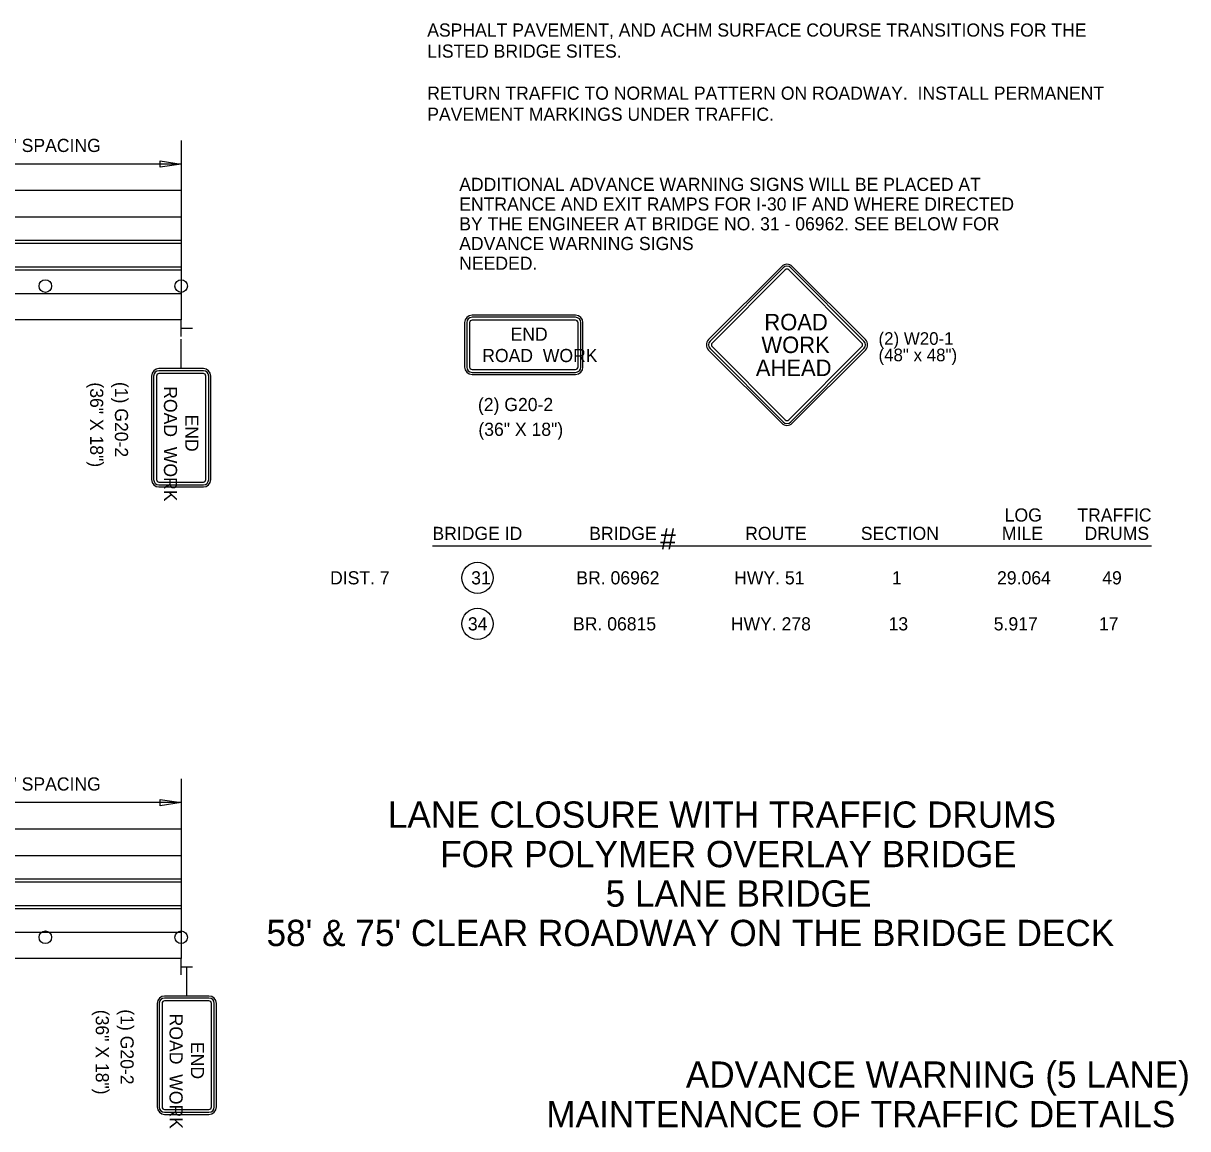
# Model space of a CAD drawing. Extents: x 1930579 to 1937984, y 596452 to 597630.
# Drawn here: x 1937427 to 1937958, y 596606 to 597111 of the extents above; entities that cross this region are included whole.
import ezdxf

# ---------------------------------------------------------------- set-up
doc = ezdxf.new("R2010")
doc.units = 0
for name, color, linetype in [('Default', 7, 'Continuous'), ('P_TC_Signs_Temporary', 7, 'Continuous'), ('R_Annotation', 7, 'Continuous')]:
    doc.layers.add(name, color=color, linetype=linetype)

msp = doc.modelspace()

# ---------------------------------------------------------------- linework, layer by layer
at = {"layer": 'Default'}
for p, q in [((1937498.74, 597057.24), (1937498.74, 596975.31)), ((1937489.08, 597045), (1937489.08, 597047.9)), ((1937489.08, 597047.9), (1937498.74, 597046.45)), ((1937498.74, 597046.45), (1937332.4, 597046.45)), ((1937498.74, 597046.45), (1937489.08, 597045)), ((1937498.74, 597034.31), (1936493.11, 597034.31)), ((1936493.11, 597022.31), (1937498.74, 597022.31)), ((1937498.74, 597011.52), (1936493.11, 597011.52)), ((1937498.74, 597010.14), (1936493.11, 597010.14)), ((1937498.74, 596999.41), (1936493.11, 596999.41)), ((1937498.74, 596998.03), (1936493.11, 596998.03)), ((1936493.11, 596987.31), (1937498.74, 596987.31)), ((1937498.74, 596975.31), (1936493.11, 596975.31)), ((1937498.63, 596975.29), (1937498.63, 596967.81)), ((1937498.74, 596971.57), (1937503.84, 596971.57)), ((1937498.74, 596765.87), (1937498.74, 596683.94)), ((1937498.74, 596755.08), (1937332.4, 596755.08)), ((1937489.08, 596753.63), (1937489.08, 596756.53)), ((1937489.08, 596756.53), (1937498.74, 596755.08)), ((1937498.74, 596755.08), (1937489.08, 596753.63)), ((1937498.74, 596742.94), (1936493.11, 596742.94)), ((1936493.11, 596730.94), (1937498.74, 596730.94)), ((1937498.74, 596720.15), (1936493.11, 596720.15)), ((1937498.74, 596718.77), (1936493.11, 596718.77)), ((1937498.74, 596708.04), (1936493.11, 596708.04)), ((1937498.74, 596706.66), (1936493.11, 596706.66)), ((1936493.11, 596695.94), (1937498.74, 596695.94)), ((1937498.74, 596683.94), (1936493.11, 596683.94)), ((1937498.63, 596683.92), (1937498.63, 596676.44)), ((1937498.74, 596680.2), (1937503.84, 596680.2))]:
    msp.add_line(p, q, dxfattribs=at)
for centre, radius in [((1937436.74, 596990.76), 2.87), ((1937498.74, 596990.76), 2.87), ((1937633.97, 596857.65), 7.11), ((1937633.97, 596836.65), 7.11), ((1937436.74, 596693.65), 2.87), ((1937498.74, 596693.65), 2.87)]:
    msp.add_circle(centre, radius, dxfattribs=at)
at = {"layer": 'P_TC_Signs_Temporary'}
for p, q in [((1937739.42, 596966.35), (1937772.83, 596999.76)), ((1937740.08, 596965.69), (1937773.5, 596999.1)), ((1937776.94, 596999.1), (1937810.35, 596965.69)), ((1937777.61, 596999.76), (1937811.02, 596966.35)), ((1937741.01, 596964.76), (1937774.42, 596998.17)), ((1937776.01, 596998.17), (1937809.43, 596964.76)), ((1937628.09, 596974.09), (1937628.09, 596953.84)), ((1937629.03, 596974.09), (1937629.03, 596953.84)), ((1937630.34, 596974.09), (1937630.34, 596953.84)), ((1937678.72, 596977.46), (1937631.47, 596977.46)), ((1937678.72, 596976.52), (1937631.47, 596976.52)), ((1937678.72, 596975.21), (1937631.47, 596975.21)), ((1937679.84, 596953.84), (1937679.84, 596974.09)), ((1937681.16, 596953.84), (1937681.16, 596974.09)), ((1937682.09, 596953.84), (1937682.09, 596974.09)), ((1937773.5, 596928.83), (1937740.08, 596962.24)), ((1937774.42, 596929.76), (1937741.01, 596963.17)), ((1937809.43, 596963.17), (1937776.01, 596929.76)), ((1937810.35, 596962.24), (1937776.94, 596928.83)), ((1937772.83, 596928.17), (1937739.42, 596961.58)), ((1937811.02, 596961.58), (1937777.61, 596928.17)), ((1937508.86, 596953.11), (1937488.61, 596953.11)), ((1937508.86, 596952.17), (1937488.61, 596952.17)), ((1937631.47, 596952.71), (1937678.72, 596952.71)), ((1937631.47, 596951.4), (1937678.72, 596951.4)), ((1937485.24, 596949.73), (1937485.24, 596902.48)), ((1937486.17, 596949.73), (1937486.17, 596902.48)), ((1937487.49, 596949.73), (1937487.49, 596902.48)), ((1937508.86, 596950.86), (1937488.61, 596950.86)), ((1937509.99, 596902.48), (1937509.99, 596949.73)), ((1937511.3, 596902.48), (1937511.3, 596949.73)), ((1937512.24, 596902.48), (1937512.24, 596949.73)), ((1937631.47, 596950.46), (1937678.72, 596950.46)), ((1937488.61, 596901.36), (1937508.86, 596901.36)), ((1937488.61, 596900.04), (1937508.86, 596900.04)), ((1937488.61, 596899.11), (1937508.86, 596899.11)), ((1937511.41, 596666.82), (1937491.16, 596666.82)), ((1937511.41, 596665.88), (1937491.16, 596665.88)), ((1937511.41, 596664.57), (1937491.16, 596664.57)), ((1937487.79, 596663.45), (1937487.79, 596616.2)), ((1937488.73, 596663.45), (1937488.73, 596616.2)), ((1937490.04, 596663.45), (1937490.04, 596616.2)), ((1937512.54, 596616.2), (1937512.54, 596663.45)), ((1937513.85, 596616.2), (1937513.85, 596663.45)), ((1937514.79, 596616.2), (1937514.79, 596663.45)), ((1937491.16, 596615.07), (1937511.41, 596615.07)), ((1937491.16, 596613.76), (1937511.41, 596613.76)), ((1937491.16, 596612.82), (1937511.41, 596612.82))]:
    msp.add_line(p, q, dxfattribs=at)
for centre, radius, start, end in [((1937775.22, 596997.37), 3.38, 45, 135), ((1937775.22, 596997.37), 2.44, 45, 135), ((1937775.22, 596997.37), 1.13, 45, 135), ((1937631.47, 596974.09), 3.37, 90, 180), ((1937631.47, 596974.09), 2.44, 90, 180), ((1937631.47, 596974.09), 1.13, 90, 180), ((1937678.72, 596974.09), 3.38, 360, 90), ((1937678.72, 596974.09), 2.44, 360, 90), ((1937678.72, 596974.09), 1.13, 360, 90), ((1937741.81, 596963.96), 3.37, 135, 225), ((1937741.81, 596963.96), 2.44, 135, 225), ((1937741.81, 596963.96), 1.12, 135, 225), ((1937808.63, 596963.96), 1.12, 315, 45), ((1937808.63, 596963.96), 2.44, 315, 45), ((1937808.63, 596963.96), 3.38, 315, 45), ((1937488.61, 596949.73), 3.37, 90, 180), ((1937488.61, 596949.73), 2.44, 90, 180), ((1937508.86, 596949.73), 3.37, 360, 90), ((1937508.86, 596949.73), 2.44, 360, 90), ((1937631.47, 596953.84), 3.37, 180, 270), ((1937631.47, 596953.84), 2.44, 180, 270), ((1937631.47, 596953.84), 1.13, 180, 270), ((1937678.72, 596953.84), 2.44, 270, 360), ((1937678.72, 596953.84), 1.13, 270, 360), ((1937678.72, 596953.84), 3.37, 270, 360), ((1937488.61, 596949.73), 1.13, 90, 180), ((1937508.86, 596949.73), 1.13, 360, 90), ((1937775.22, 596930.55), 3.37, 225, 315), ((1937775.22, 596930.55), 2.44, 225, 315), ((1937775.22, 596930.55), 1.13, 225, 315), ((1937488.61, 596902.48), 3.37, 180, 270), ((1937488.61, 596902.48), 2.44, 180, 270), ((1937488.61, 596902.48), 1.13, 180, 270), ((1937508.86, 596902.48), 2.44, 270, 360), ((1937508.86, 596902.48), 1.13, 270, 360), ((1937508.86, 596902.48), 3.38, 270, 360), ((1937491.16, 596663.45), 3.37, 90, 180), ((1937491.16, 596663.45), 2.44, 90, 180), ((1937491.16, 596663.45), 1.13, 90, 180), ((1937511.41, 596663.45), 3.37, 360, 90), ((1937511.41, 596663.45), 2.44, 360, 90), ((1937511.41, 596663.45), 1.13, 360, 90), ((1937491.16, 596616.2), 3.37, 180, 270), ((1937491.16, 596616.2), 2.44, 180, 270), ((1937491.16, 596616.2), 1.13, 180, 270), ((1937511.41, 596616.2), 2.44, 270, 360), ((1937511.41, 596616.2), 1.13, 270, 360), ((1937511.41, 596616.2), 3.38, 270, 360)]:
    msp.add_arc(centre, radius, start, end, dxfattribs=at)
at = {"layer": 'R_Annotation'}
for p, q in [((1937498.74, 596953.11), (1937498.74, 596966.48)), ((1937613.4, 596872.21), (1937941.61, 596872.21)), ((1937501.29, 596666.82), (1937501.29, 596680.2))]:
    msp.add_line(p, q, dxfattribs=at)

# ---------------------------------------------------------------- texts
at = {"layer": 'Default'}
for p in [(1937335.13, 597051.95), (1937335.13, 596760.58)]:
    msp.add_text("TRAFFIC DRUMS @ 60' SPACING", height=6, rotation=360, dxfattribs=at).set_placement(p)
for s, p in [('LANE CLOSURE WITH TRAFFIC DRUMS', (1937593.05, 596743.6)), ('FOR POLYMER OVERLAY BRIDGE', (1937616.95, 596725.6)), ('5 LANE BRIDGE', (1937692.45, 596707.6)), ("58' & 75' CLEAR ROADWAY ON THE BRIDGE DECK", (1937537.68, 596689.6))]:
    msp.add_text(s, height=12, dxfattribs=at).set_placement(p)
at = {"layer": 'P_TC_Signs_Temporary'}
for s, height, p in [('ROAD', 7.5, (1937764.87, 596970.59)), ('END', 6, (1937649.06, 596965.84)), ('WORK', 7.5, (1937763.54, 596960.21)), ('AHEAD', 7.5, (1937761, 596949.71))]:
    msp.add_text(s, height=height, dxfattribs=at).set_placement(p)
for s, rotation, p in [('ROAD  WORK', 360, (1937636.13, 596956.09)), ('ROAD  WORK', 270, (1937490.86, 596945.07)), ('END', 270, (1937500.61, 596932.14)), ('ROAD  WORK', 270, (1937493.41, 596658.78)), ('END', 270, (1937503.16, 596645.85))]:
    msp.add_text(s, height=6, rotation=rotation, dxfattribs=at).set_placement(p)
at = {"layer": 'R_Annotation'}
for s, height, rotation, p in [('ASPHALT PAVEMENT, AND ACHM SURFACE COURSE TRANSITIONS FOR THE ', 6, 360, (1937611.03, 597104.59)), ('LISTED BRIDGE SITES.', 6, 360, (1937611.03, 597094.99)), ('RETURN TRAFFIC TO NORMAL PATTERN ON ROADWAY.  INSTALL PERMANENT', 6, 360, (1937611.03, 597075.79)), ('PAVEMENT MARKINGS UNDER TRAFFIC.', 6, 360, (1937611.03, 597066.19)), ('ADDITIONAL ADVANCE WARNING SIGNS WILL BE PLACED AT ', 6, 360, (1937625.63, 597034.19)), ('ENTRANCE AND EXIT RAMPS FOR I-30 IF AND WHERE DIRECTED', 6, 360, (1937625.63, 597025.19)), ('BY THE ENGINEER AT BRIDGE NO. 31 - 06962. SEE BELOW FOR ', 6, 360, (1937625.63, 597016.19)), ('ADVANCE WARNING SIGNS ', 6, 360, (1937625.63, 597007.19)), ('NEEDED.', 6, 360, (1937625.63, 596998.19)), ('(2) W20-1', 5.76, 360, (1937816.99, 596963.96)), ('(48" x 48")', 5.76, 360, (1937816.99, 596956.47)), ('(36" X 18")', 6, 270, (1937457.19, 596946.83)), ('(1) G20-2', 6, 270, (1937468.49, 596947.03)), ('(2) G20-2', 6, 360, (1937634.17, 596933.72)), ('(36" X 18")', 6, 360, (1937634.37, 596922.42)), ('LOG', 6, 360, (1937874.57, 596883.32)), ('TRAFFIC', 6, 360, (1937907.73, 596883.32)), ('BRIDGE ID', 6, 360, (1937613.4, 596874.92)), ('BRIDGE ', 6, 360, (1937684.95, 596874.92)), ('#', 9.6, 360, (1937717.37, 596870.67)), ('ROUTE', 6, 360, (1937756.12, 596874.92)), ('SECTION', 6, 360, (1937808.9, 596874.92)), ('MILE', 6, 360, (1937873.31, 596874.92)), ('DRUMS', 6, 360, (1937911.06, 596874.92)), ('DIST. 7', 6, 360, (1937566.69, 596854.65)), ('31', 6, 360, (1937631.09, 596854.65)), ('BR. 06962', 6, 360, (1937679.09, 596854.65)), ('29.064', 6, 360, (1937871.09, 596854.65)), ('49', 6, 360, (1937919.09, 596854.65)), ('HWY. 51', 6, 360, (1937751.09, 596854.65)), ('1', 6, 360, (1937823.09, 596854.65)), ('34', 6, 360, (1937629.58, 596833.65)), ('BR. 06815', 6, 360, (1937677.58, 596833.65)), ('HWY. 278', 6, 360, (1937749.58, 596833.65)), ('13', 6, 360, (1937821.58, 596833.65)), ('5.917', 6, 360, (1937869.58, 596833.65)), ('17', 6, 360, (1937917.58, 596833.65)), ('(36" X 18")', 6, 270, (1937459.74, 596660.55)), ('(1) G20-2', 6, 270, (1937471.05, 596660.75)), ('ADVANCE WARNING (5 LANE)', 12, 360, (1937729.05, 596624.97)), ('MAINTENANCE OF TRAFFIC DETAILS', 12, 360, (1937665.37, 596606.97))]:
    msp.add_text(s, height=height, rotation=rotation, dxfattribs=at).set_placement(p)

doc.saveas('drawing.dxf')
